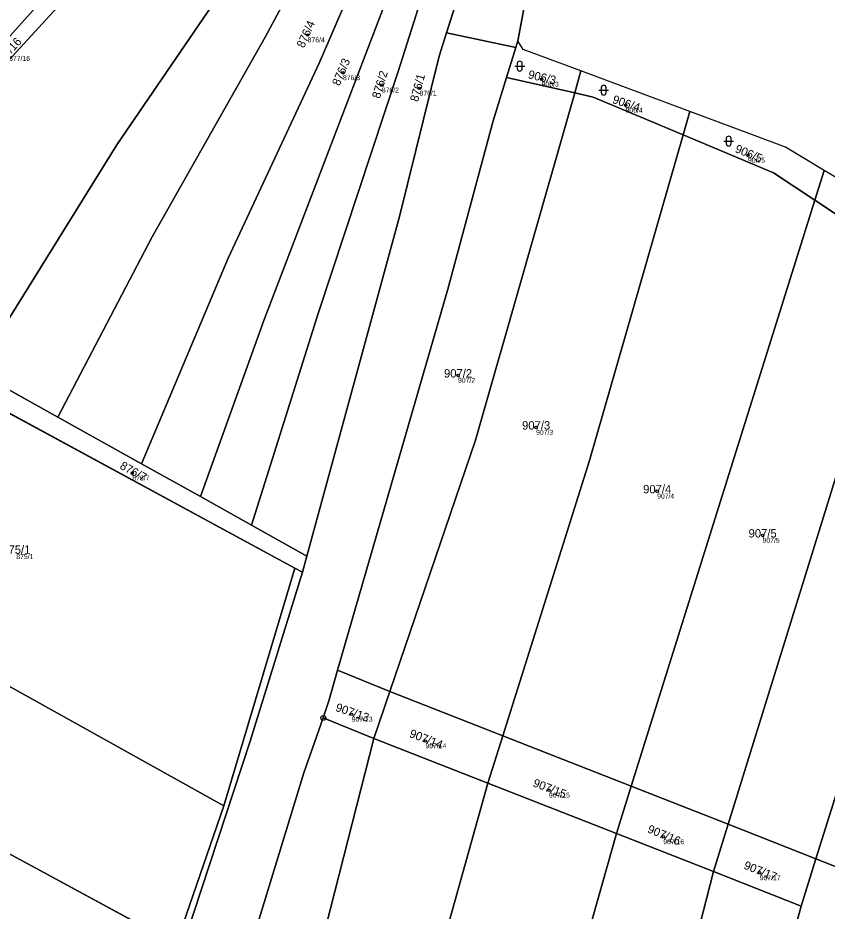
# Model space of a CAD drawing. Extents: x -603967 to -594699, y -1179315 to -1165625.
# Drawn here: x -597432 to -597268.2, y -1171582.4 to -1171401.5 of the extents above; entities that cross this region are included whole.
import ezdxf

# ---------------------------------------------------------------- set-up
doc = ezdxf.new("R2010")
doc.units = 0
for name, color, linetype in [('Definiční body', 7, 'Continuous'), ('Hranice parcel', 7, 'Continuous'), ('Parcelní čísla', 7, 'Continuous'), ('Polygon ku', 7, 'Continuous'), ('Polygon parcely', 7, 'Continuous'), ('Značky bodu BP', 7, 'Continuous'), ('Značky kultur', 7, 'Continuous')]:
    doc.layers.add(name, color=color, linetype=linetype)

msp = doc.modelspace()

# ---------------------------------------------------------------- linework, layer by layer
at = {"layer": 'Definiční body'}
for centre in [(-597373.34, -1171404.92994), (-597366.2, -1171412.58994), (-597358.33, -1171415.09994), (-597325.98, -1171413.90994), (-597350.7, -1171415.71994), (-597308.99, -1171419.17994), (-597284.23, -1171429.31994), (-597342.91, -1171473.88994), (-597327.11, -1171484.42994), (-597408.82, -1171493.67994), (-597302.61, -1171497.33994), (-597281.27, -1171506.29994), (-597364.42, -1171542.53994), (-597349.5, -1171547.91994), (-597324.5, -1171557.92994), (-597301.37, -1171567.34994), (-597281.85, -1171574.64994)]:
    msp.add_circle(centre, 0.25, dxfattribs=at)
at = {"layer": 'Hranice parcel'}
for p, q in [((-597320.67, -1171326.8), (-597345.23, -1171404.47)), ((-597346.74, -1171409.25), (-597345.23, -1171404.47)), ((-597345.23, -1171404.47), (-597331.22, -1171407.48)), ((-597331.22, -1171407.48), (-597333.09, -1171413.53)), ((-597330.79, -1171406.09), (-597331.22, -1171407.48)), ((-597354.78, -1171441.7), (-597346.74, -1171409.25)), ((-597318.04, -1171412.22), (-597327.91, -1171408.54)), ((-597319.3, -1171416.66), (-597318.04, -1171412.22)), ((-597296.01, -1171420.45), (-597318.04, -1171412.22)), ((-597333.09, -1171413.53), (-597319.3, -1171416.66)), ((-597297.36, -1171425.16), (-597296.01, -1171420.45)), ((-597283.34, -1171425.18), (-597296.01, -1171420.45)), ((-597270.67, -1171438.4), (-597268.78, -1171432.38)), ((-597267.64, -1171433.06), (-597268.78, -1171432.38)), ((-597307.87, -1171557.1), (-597270.67, -1171438.4)), ((-597373.51, -1171510.48), (-597354.78, -1171441.7)), ((-597288.25, -1171564.8), (-597252.37, -1171448.97)), ((-597270.47, -1171571.83), (-597234.55, -1171457.56)), ((-597375.91, -1171512.92), (-597474.54, -1171459.44)), ((-597440.48, -1171473.06), (-597423.87, -1171482.34)), ((-597423.87, -1171482.34), (-597406.98, -1171491.78)), ((-597406.98, -1171491.78), (-597395.05, -1171498.44)), ((-597395.05, -1171498.44), (-597384.69, -1171504.23)), ((-597497.92, -1171501.14), (-597390.32, -1171561.09)), ((-597384.69, -1171504.23), (-597373.51, -1171510.48)), ((-597374.4, -1171513.74), (-597373.51, -1171510.48)), ((-597390.32, -1171561.09), (-597375.91, -1171512.92)), ((-597374.4, -1171513.74), (-597375.91, -1171512.92)), ((-597399.98, -1171589.1), (-597512.89, -1171527.89)), ((-597367.3, -1171533.62), (-597356.69, -1171537.94)), ((-597359.93, -1171547.4), (-597356.69, -1171537.94)), ((-597356.69, -1171537.94), (-597333.87, -1171546.9)), ((-597370.17, -1171543.27), (-597359.93, -1171547.4)), ((-597336.86, -1171556.45), (-597333.87, -1171546.9)), ((-597333.87, -1171546.9), (-597307.87, -1171557.1)), ((-597359.93, -1171547.4), (-597336.86, -1171556.45)), ((-597336.86, -1171556.45), (-597310.85, -1171566.66)), ((-597310.85, -1171566.66), (-597307.87, -1171557.1)), ((-597307.87, -1171557.1), (-597288.25, -1171564.8)), ((-597399.98, -1171589.1), (-597390.32, -1171561.09)), ((-597291.18, -1171574.4), (-597288.25, -1171564.8)), ((-597288.25, -1171564.8), (-597270.47, -1171571.83)), ((-597310.85, -1171566.66), (-597291.18, -1171574.4)), ((-597273.45, -1171581.37), (-597270.47, -1171571.83)), ((-597270.47, -1171571.83), (-597262.91, -1171574.78)), ((-597291.18, -1171574.4), (-597273.45, -1171581.37))]:
    msp.add_line(p, q, dxfattribs=at)
for points in [[(-597299.7, -1171268.37), (-597318.05, -1171289.57), (-597411.95, -1171427.19), (-597440.48, -1171473.06)], [(-597299.49, -1171268.52), (-597314.8, -1171287.53), (-597330.02, -1171313.79), (-597357.67, -1171360.22), (-597381.95, -1171405.38), (-597404.84, -1171445.83), (-597423.87, -1171482.34)], [(-597299.13, -1171268.78), (-597312.85, -1171288.16), (-597349.41, -1171360.64), (-597371.03, -1171410.66), (-597389.44, -1171450.14), (-597406.98, -1171491.78)], [(-597298.77, -1171269.04), (-597310.44, -1171287.85), (-597316.72, -1171300.39), (-597345.4, -1171366.29), (-597382.2, -1171462.76), (-597395.05, -1171498.44)], [(-597298.06, -1171269.55), (-597309.18, -1171287.29), (-597315.19, -1171299.92), (-597342.1, -1171371.44), (-597355.02, -1171412.3), (-597371.24, -1171461.36), (-597384.69, -1171504.23)], [(-597311.98, -1171342.64), (-597328.5, -1171393.81), (-597330.79, -1171406.09)], [(-597400.18, -1171364.14), (-597404.12, -1171372.23), (-597446.62, -1171419.62), (-597477.72, -1171457.61)], [(-597400.25, -1171373.28), (-597446.51, -1171423.81), (-597471.59, -1171455.69)], [(-597327.91, -1171408.54), (-597329.75, -1171407.85), (-597330.79, -1171406.09)], [(-597333.09, -1171413.53), (-597335.82, -1171422.34), (-597344.97, -1171456.39), (-597367.3, -1171533.62)], [(-597356.69, -1171537.94), (-597339.37, -1171487.01), (-597319.3, -1171416.66)], [(-597319.3, -1171416.66), (-597315.57, -1171417.5), (-597297.36, -1171425.16)], [(-597333.87, -1171546.9), (-597316.32, -1171491.11), (-597297.36, -1171425.16)], [(-597297.36, -1171425.16), (-597279.07, -1171432.86), (-597270.67, -1171438.4)], [(-597268.78, -1171432.38), (-597276.66, -1171427.68), (-597283.34, -1171425.18)], [(-597270.67, -1171438.4), (-597260.9, -1171444.85), (-597252.37, -1171448.97)], [(-597415.13, -1171657.46), (-597399.75, -1171592.91), (-597384.99, -1171547.96), (-597374.4, -1171513.74)], [(-597367.3, -1171533.62), (-597369.02, -1171539.57), (-597370.17, -1171543.27)], [(-597370.17, -1171543.27), (-597374.11, -1171554.38), (-597388.86, -1171602.72), (-597412.23, -1171696.79), (-597426.54, -1171820.61)], [(-597359.93, -1171547.4), (-597380.99, -1171630.08), (-597394.37, -1171681.58), (-597412.78, -1171803.72), (-597426.85, -1171871.65)], [(-597336.86, -1171556.45), (-597374.62, -1171691.55), (-597400.35, -1171808.84), (-597426.11, -1171896.14)], [(-597310.85, -1171566.66), (-597332.61, -1171643.76), (-597373.69, -1171818.16), (-597402.42, -1171905), (-597414.34, -1171933.48), (-597424.21, -1171953.3)], [(-597291.18, -1171574.4), (-597355.56, -1171825.87), (-597380.96, -1171906.06), (-597395, -1171941.85), (-597423.03, -1171989.05)], [(-597273.45, -1171581.37), (-597308.87, -1171710.93), (-597337.88, -1171834.13), (-597361.28, -1171910.05), (-597379.95, -1171953.1), (-597422.14, -1172015.75)]]:
    msp.add_lwpolyline(points, dxfattribs=at)
at = {"layer": 'Polygon ku'}
msp.add_lwpolyline([(-597158.58, -1171488.63), (-597164.6, -1171485.62), (-597176.07, -1171479.94), (-597185.07, -1171475.59), (-597194.38, -1171470.95), (-597199.62, -1171468.4), (-597206.66, -1171464.72), (-597225.54, -1171455.45), (-597232.11, -1171452.17), (-597232.76, -1171451.85), (-597249.54, -1171443.48), (-597250.52, -1171442.99), (-597253.47, -1171441.52), (-597267.64, -1171433.06), (-597268.78, -1171432.38), (-597276.66, -1171427.68), (-597283.34, -1171425.18), (-597296.01, -1171420.45), (-597318.04, -1171412.22), (-597327.91, -1171408.54), (-597329.75, -1171407.85), (-597330.79, -1171406.09), (-597328.5, -1171393.81)], dxfattribs=at)
at = {"layer": 'Polygon parcely'}
for points in [[(-597345.23, -1171404.47), (-597331.22, -1171407.48), (-597330.79, -1171406.09), (-597328.5, -1171393.81), (-597311.98, -1171342.64), (-597304.43, -1171319.02), (-597299.44, -1171304.37), (-597293.33, -1171286.58), (-597284.6, -1171271.09), (-597288.43, -1171266.96), (-597292.07, -1171263.03), (-597293.47, -1171261.54), (-597295.13, -1171264.88), (-597297.58, -1171269.89), (-597304.13, -1171283.29), (-597311.3, -1171300.77), (-597320.67, -1171326.8)], [(-597299.7, -1171268.37), (-597300.38, -1171267.91), (-597305.37, -1171272.56), (-597400.25, -1171373.28), (-597446.51, -1171423.81), (-597471.59, -1171455.69), (-597440.48, -1171473.06), (-597411.95, -1171427.19), (-597318.05, -1171289.57)], [(-597299.49, -1171268.52), (-597299.7, -1171268.37), (-597318.05, -1171289.57), (-597411.95, -1171427.19), (-597440.48, -1171473.06), (-597423.87, -1171482.34), (-597404.84, -1171445.83), (-597381.95, -1171405.38), (-597357.67, -1171360.22), (-597330.02, -1171313.79), (-597314.8, -1171287.53)], [(-597357.67, -1171360.22), (-597381.95, -1171405.38), (-597404.84, -1171445.83), (-597423.87, -1171482.34), (-597406.98, -1171491.78), (-597389.44, -1171450.14), (-597371.03, -1171410.66), (-597349.41, -1171360.64), (-597312.85, -1171288.16), (-597299.13, -1171268.78), (-597299.49, -1171268.52), (-597314.8, -1171287.53), (-597330.02, -1171313.79)], [(-597299.13, -1171268.78), (-597312.85, -1171288.16), (-597349.41, -1171360.64), (-597371.03, -1171410.66), (-597389.44, -1171450.14), (-597406.98, -1171491.78), (-597395.05, -1171498.44), (-597382.2, -1171462.76), (-597345.4, -1171366.29), (-597316.72, -1171300.39), (-597310.44, -1171287.85), (-597298.77, -1171269.04)], [(-597345.4, -1171366.29), (-597382.2, -1171462.76), (-597395.05, -1171498.44), (-597384.69, -1171504.23), (-597371.24, -1171461.36), (-597355.02, -1171412.3), (-597342.1, -1171371.44), (-597315.19, -1171299.92), (-597309.18, -1171287.29), (-597298.06, -1171269.55), (-597298.77, -1171269.04), (-597310.44, -1171287.85), (-597316.72, -1171300.39)], [(-597346.74, -1171409.25), (-597345.23, -1171404.47), (-597320.67, -1171326.8), (-597311.3, -1171300.77), (-597304.13, -1171283.29), (-597297.58, -1171269.89), (-597298.06, -1171269.55), (-597309.18, -1171287.29), (-597315.19, -1171299.92), (-597342.1, -1171371.44), (-597355.02, -1171412.3), (-597371.24, -1171461.36), (-597384.69, -1171504.23), (-597373.51, -1171510.48), (-597354.78, -1171441.7)], [(-597446.62, -1171419.62), (-597477.72, -1171457.61), (-597474.54, -1171459.44), (-597471.59, -1171455.69), (-597446.51, -1171423.81), (-597400.25, -1171373.28), (-597393.07, -1171357.03), (-597400.18, -1171364.14), (-597404.12, -1171372.23)], [(-597403.24, -1171367.24), (-597413.26, -1171377.4), (-597434.49, -1171398.91), (-597442.99, -1171407.52), (-597452.88, -1171418.22), (-597467.22, -1171433.75), (-597469.94, -1171437.13), (-597481.29, -1171451.23), (-597483.39, -1171454.62), (-597477.72, -1171457.61), (-597446.62, -1171419.62), (-597404.12, -1171372.23), (-597400.18, -1171364.14)], [(-597333.09, -1171413.53), (-597319.3, -1171416.66), (-597318.04, -1171412.22), (-597327.91, -1171408.54), (-597329.75, -1171407.85), (-597330.79, -1171406.09), (-597331.22, -1171407.48)], [(-597296.01, -1171420.45), (-597318.04, -1171412.22), (-597319.3, -1171416.66), (-597315.57, -1171417.5), (-597297.36, -1171425.16)], [(-597344.97, -1171456.39), (-597367.3, -1171533.62), (-597356.69, -1171537.94), (-597339.37, -1171487.01), (-597319.3, -1171416.66), (-597333.09, -1171413.53), (-597335.82, -1171422.34)], [(-597333.87, -1171546.9), (-597316.32, -1171491.11), (-597297.36, -1171425.16), (-597315.57, -1171417.5), (-597319.3, -1171416.66), (-597339.37, -1171487.01), (-597356.69, -1171537.94)], [(-597283.34, -1171425.18), (-597296.01, -1171420.45), (-597297.36, -1171425.16), (-597279.07, -1171432.86), (-597270.67, -1171438.4), (-597268.78, -1171432.38), (-597276.66, -1171427.68)], [(-597307.87, -1171557.1), (-597270.67, -1171438.4), (-597279.07, -1171432.86), (-597297.36, -1171425.16), (-597316.32, -1171491.11), (-597333.87, -1171546.9)], [(-597268.78, -1171432.38), (-597270.67, -1171438.4), (-597260.9, -1171444.85), (-597252.37, -1171448.97), (-597250.52, -1171442.99), (-597253.47, -1171441.52), (-597267.64, -1171433.06)], [(-597288.25, -1171564.8), (-597252.37, -1171448.97), (-597260.9, -1171444.85), (-597270.67, -1171438.4), (-597307.87, -1171557.1)], [(-597234.55, -1171457.56), (-597252.37, -1171448.97), (-597288.25, -1171564.8), (-597270.47, -1171571.83)], [(-597374.4, -1171513.74), (-597373.51, -1171510.48), (-597384.69, -1171504.23), (-597395.05, -1171498.44), (-597406.98, -1171491.78), (-597423.87, -1171482.34), (-597440.48, -1171473.06), (-597471.59, -1171455.69), (-597474.54, -1171459.44), (-597375.91, -1171512.92)], [(-597262.91, -1171574.78), (-597227.3, -1171461.06), (-597234.55, -1171457.56), (-597270.47, -1171571.83)], [(-597497.92, -1171501.14), (-597390.32, -1171561.09), (-597375.91, -1171512.92), (-597474.54, -1171459.44)], [(-597512.89, -1171527.89), (-597399.98, -1171589.1), (-597390.32, -1171561.09), (-597497.92, -1171501.14), (-597512.55, -1171527.22)], [(-597415.13, -1171657.46), (-597399.75, -1171592.91), (-597384.99, -1171547.96), (-597374.4, -1171513.74), (-597375.91, -1171512.92), (-597390.32, -1171561.09), (-597399.98, -1171589.1), (-597416.13, -1171656.92)], [(-597543.52, -1171588.03), (-597416.13, -1171656.92), (-597399.98, -1171589.1), (-597512.89, -1171527.89)], [(-597370.17, -1171543.27), (-597359.93, -1171547.4), (-597356.69, -1171537.94), (-597367.3, -1171533.62), (-597369.02, -1171539.57)], [(-597336.86, -1171556.45), (-597333.87, -1171546.9), (-597356.69, -1171537.94), (-597359.93, -1171547.4)], [(-597388.86, -1171602.72), (-597412.23, -1171696.79), (-597426.54, -1171820.61), (-597426.85, -1171871.65), (-597412.78, -1171803.72), (-597394.37, -1171681.58), (-597380.99, -1171630.08), (-597359.93, -1171547.4), (-597370.17, -1171543.27), (-597374.11, -1171554.38)], [(-597307.87, -1171557.1), (-597333.87, -1171546.9), (-597336.86, -1171556.45), (-597310.85, -1171566.66)], [(-597426.85, -1171871.65), (-597426.86, -1171873.4), (-597426.11, -1171896.14), (-597400.35, -1171808.84), (-597374.62, -1171691.55), (-597336.86, -1171556.45), (-597359.93, -1171547.4), (-597380.99, -1171630.08), (-597394.37, -1171681.58), (-597412.78, -1171803.72)], [(-597424.21, -1171953.3), (-597414.34, -1171933.48), (-597402.42, -1171905), (-597373.69, -1171818.16), (-597332.61, -1171643.76), (-597310.85, -1171566.66), (-597336.86, -1171556.45), (-597374.62, -1171691.55), (-597400.35, -1171808.84), (-597426.11, -1171896.14)], [(-597291.18, -1171574.4), (-597288.25, -1171564.8), (-597307.87, -1171557.1), (-597310.85, -1171566.66)], [(-597273.45, -1171581.37), (-597270.47, -1171571.83), (-597288.25, -1171564.8), (-597291.18, -1171574.4)], [(-597424.21, -1171953.3), (-597423.03, -1171989.05), (-597395, -1171941.85), (-597380.96, -1171906.06), (-597355.56, -1171825.87), (-597291.18, -1171574.4), (-597310.85, -1171566.66), (-597332.61, -1171643.76), (-597373.69, -1171818.16), (-597402.42, -1171905), (-597414.34, -1171933.48)], [(-597421.72, -1172028.43), (-597395.91, -1171993.7), (-597372.28, -1171956.46), (-597353.6, -1171914.79), (-597328.53, -1171829.85), (-597286.8, -1171661.88), (-597265.92, -1171584.24), (-597262.91, -1171574.78), (-597270.47, -1171571.83), (-597273.45, -1171581.37), (-597308.87, -1171710.93), (-597337.88, -1171834.13), (-597361.28, -1171910.05), (-597379.95, -1171953.1), (-597422.14, -1172015.75)], [(-597422.14, -1172015.75), (-597379.95, -1171953.1), (-597361.28, -1171910.05), (-597337.88, -1171834.13), (-597308.87, -1171710.93), (-597273.45, -1171581.37), (-597291.18, -1171574.4), (-597355.56, -1171825.87), (-597380.96, -1171906.06), (-597395, -1171941.85), (-597423.03, -1171989.05)]]:
    msp.add_lwpolyline(points, close=True, dxfattribs=at)
msp.add_lwpolyline([(-597388.86, -1171602.72), (-597374.11, -1171554.38), (-597370.17, -1171543.27), (-597369.02, -1171539.57), (-597367.3, -1171533.62), (-597344.97, -1171456.39), (-597335.82, -1171422.34), (-597333.09, -1171413.53), (-597331.22, -1171407.48), (-597345.23, -1171404.47), (-597346.74, -1171409.25), (-597354.78, -1171441.7), (-597373.51, -1171510.48), (-597374.4, -1171513.74), (-597384.99, -1171547.96), (-597399.75, -1171592.91)], dxfattribs=at)
at = {"layer": 'Značky bodu BP'}
for radius in [0.5, 0.0303]:
    msp.add_circle((-597370.17, -1171543.26988), radius, dxfattribs=at)
at = {"layer": 'Značky kultur'}
for p, q in [((-597331.421, -1171411.231), (-597329.419, -1171411.231)), ((-597330.921, -1171410.731), (-597330.921, -1171411.732)), ((-597329.919, -1171411.732), (-597329.919, -1171410.731)), ((-597314.431, -1171416.111), (-597312.429, -1171416.111)), ((-597313.931, -1171415.611), (-597313.931, -1171416.612)), ((-597312.929, -1171416.612), (-597312.929, -1171415.611)), ((-597289.141, -1171426.421), (-597287.139, -1171426.421)), ((-597288.641, -1171425.921), (-597288.641, -1171426.922)), ((-597287.639, -1171426.922), (-597287.639, -1171425.921))]:
    msp.add_line(p, q, dxfattribs=at)
for centre, start, end in [((-597330.42, -1171410.7309), 0, 180), ((-597330.42, -1171411.7309), 180, 359.9878861), ((-597313.43, -1171415.6109), 0, 180), ((-597313.43, -1171416.6109), 180, 359.9878861), ((-597288.14, -1171425.9209), 0, 180), ((-597288.14, -1171426.9209), 180, 359.9878861)]:
    msp.add_arc(centre, 0.5, start, end, dxfattribs=at)

# ---------------------------------------------------------------- texts
at = {"layer": 'Definiční body'}
for s, p in [('876/4', (-597373.34, -1171406.419)), ('877/16', (-597433.76, -1171410.179)), ('876/3', (-597366.2, -1171414.079)), ('906/3', (-597325.98, -1171415.399)), ('876/2', (-597358.33, -1171416.589)), ('876/1', (-597350.7, -1171417.209)), ('906/4', (-597308.99, -1171420.669)), ('906/5', (-597284.23, -1171430.809)), ('907/2', (-597342.91, -1171475.379)), ('907/3', (-597327.11, -1171485.919)), ('876/7', (-597408.82, -1171495.169)), ('907/4', (-597302.61, -1171498.829)), ('907/5', (-597281.27, -1171507.789)), ('875/1', (-597432.31, -1171511.089)), ('907/13', (-597364.42, -1171544.029)), ('907/14', (-597349.5, -1171549.409)), ('907/15', (-597324.5, -1171559.419)), ('907/16', (-597301.37, -1171568.839)), ('907/17', (-597281.85, -1171576.139))]:
    msp.add_text(s, height=0.999996, dxfattribs=at).set_placement(p)
at = {"layer": 'Parcelní čísla'}
for s, rotation, p in [('876/4', 66, (-597374.105, -1171407.693)), ('877/16', 48, (-597435.763, -1171411.55)), ('876/3', 66.9999972, (-597366.916, -1171415.366)), ('876/2', 73, (-597358.752, -1171417.936)), ('906/3', 347, (-597328.839, -1171413.686)), ('876/1', 75, (-597351.023, -1171418.569)), ('906/4', 340.9999972, (-597311.809, -1171418.658)), ('906/5', 337, (-597287.006, -1171428.603)), ('876/7', 331, (-597411.506, -1171492.676)), ('907/13', 340.9999972, (-597367.835, -1171541.813)), ('907/14', 339, (-597352.888, -1171547.074)), ('907/15', 339, (-597327.888, -1171557.084)), ('907/16', 337, (-597304.726, -1171566.386)), ('907/17', 338, (-597285.223, -1171573.745))]:
    msp.add_text(s, height=1.699998, rotation=rotation, dxfattribs=at).set_placement(p)
for s, p in [('907/2', (-597345.746, -1171474.315)), ('907/3', (-597329.946, -1171484.855)), ('907/4', (-597305.446, -1171497.765)), ('907/5', (-597284.106, -1171506.725)), ('875/1', (-597435.146, -1171510.025))]:
    msp.add_text(s, height=1.699998, dxfattribs=at).set_placement(p)

doc.saveas('drawing.dxf')
